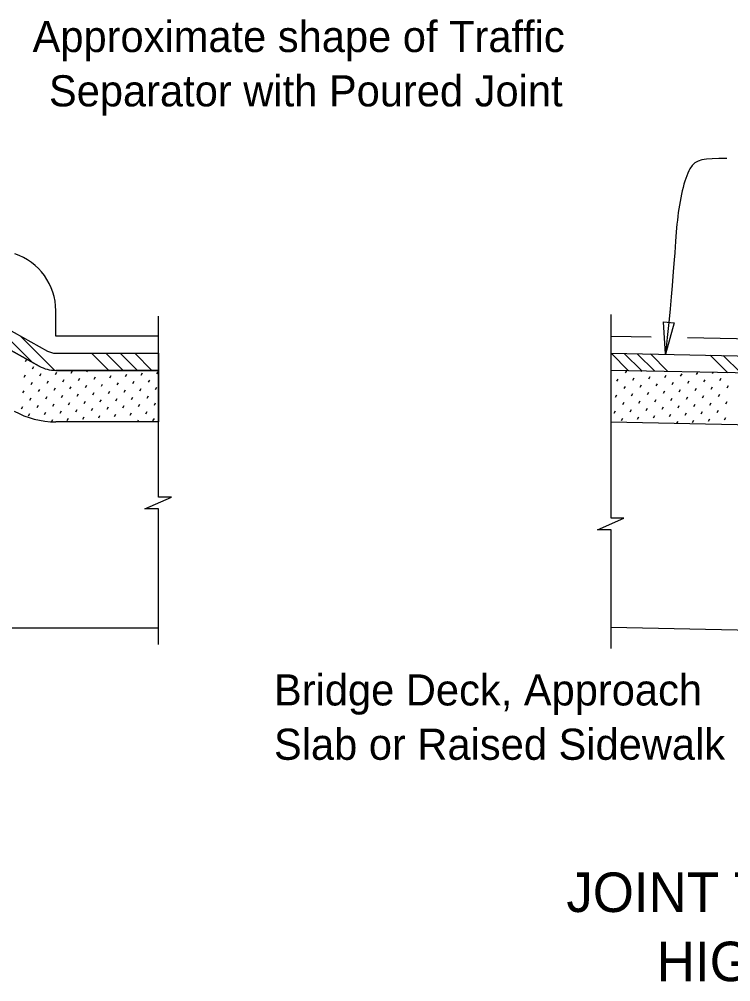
# Model space of a CAD drawing. Extents: x -7.9 to 27, y -3.1 to 14.6.
# Drawn here: x 9.806 to 11.534, y 7.031 to 9.368 of the extents above; entities that cross this region are included whole.
import ezdxf

# ---------------------------------------------------------------- set-up
doc = ezdxf.new("R2010")
doc.units = 0
for name, color, linetype in [('Patterning', 7, 'Continuous'), ('PlotBorder_dp', 7, 'Continuous'), ('TextMisc', 7, 'Continuous')]:
    doc.layers.add(name, color=color, linetype=linetype)

msp = doc.modelspace()

# ---------------------------------------------------------------- linework, layer by layer
at = {"layer": 'Patterning'}
for p, q in [((9.8946, 8.5989), (9.8946, 8.6605)), ((11.2433, 8.599), (11.3407, 8.597)), ((11.429, 8.5953), (13.3109, 8.5576)), ((5.2585, 7.8906), (10.1444, 7.8906)), ((14.5636, 7.8243), (11.2433, 7.8907))]:
    msp.add_line(p, q, dxfattribs=at)
msp.add_lwpolyline([(10.1445, 8.599), (9.8947, 8.599)], dxfattribs=at)
msp.add_arc((9.7488, 8.6606), 0.1458, 0, 71.5651, dxfattribs=at)
at = {"layer": 'PlotBorder_dp'}
for points in [[(11.2432, 7.8402), (11.2432, 8.1284), (11.2102, 8.1284), (11.2742, 8.1567), (11.2432, 8.1567), (11.2432, 8.6517)], [(10.1444, 7.85), (10.1444, 8.1797), (10.1113, 8.1797), (10.1753, 8.208), (10.1444, 8.208), (10.1444, 8.6476)]]:
    msp.add_lwpolyline(points, dxfattribs=at)
msp.add_lwpolyline([(11.3966, 8.631), (11.3755, 8.5546), (11.3703, 8.6337)], close=True, dxfattribs=at)
msp.add_open_spline([(11.5243, 9.0302), (11.4677, 9.0302), (11.4308, 9.0302), (11.399, 8.8797), (11.3988, 8.7821), (11.3755, 8.5546)], degree=3, dxfattribs=at)
at = {"layer": 'TextMisc'}
for p, q in [((9.1426, 8.9691), (9.8744, 8.5625)), ((9.8542, 8.5261), (9.1405, 8.9226)), ((9.1405, 8.9226), (9.8542, 8.5261)), ((9.7296, 8.643), (9.8369, 8.5357)), ((9.8083, 8.5993), (9.8913, 8.5163)), ((9.8947, 8.5573), (10.1445, 8.5573)), ((9.9814, 8.5573), (10.0231, 8.5156)), ((10.0164, 8.5573), (10.0581, 8.5156)), ((10.0514, 8.5573), (10.0931, 8.5156)), ((10.0864, 8.5573), (10.1281, 8.5156)), ((10.1445, 8.5573), (10.1445, 8.5156)), ((11.2433, 8.5573), (11.2858, 8.5147)), ((11.2433, 8.5573), (13.3732, 8.5146)), ((11.2751, 8.5566), (11.3177, 8.5141)), ((9.821, 8.537), (9.8242, 8.5426)), ((11.307, 8.556), (11.3495, 8.5134)), ((11.3388, 8.5554), (11.3813, 8.5128)), ((11.4839, 8.5525), (11.5264, 8.5099)), ((11.5157, 8.5518), (11.5583, 8.5093)), ((9.8384, 8.5196), (9.8417, 8.5252)), ((9.8941, 8.5053), (9.8973, 8.5109)), ((10.1445, 8.5156), (9.8947, 8.5156)), ((9.8947, 8.5156), (10.1445, 8.5156)), ((9.9322, 8.5086), (9.9354, 8.5142)), ((9.9704, 8.5118), (9.9725, 8.5156)), ((10.0085, 8.5151), (10.0088, 8.5156)), ((10.1404, 8.5073), (10.1437, 8.5129)), ((10.1445, 8.5156), (10.1445, 8.3906)), ((13.3724, 8.4729), (11.2433, 8.5156)), ((11.2785, 8.5099), (11.2814, 8.5148)), ((11.3172, 8.5132), (11.3177, 8.5141)), ((11.4509, 8.5052), (11.4542, 8.5108)), ((11.4896, 8.5084), (11.4909, 8.5106)), ((9.8177, 8.4989), (9.821, 8.5045)), ((9.8352, 8.4814), (9.8384, 8.487)), ((9.8559, 8.5021), (9.8591, 8.5077)), ((9.8734, 8.4846), (9.8766, 8.4902)), ((9.9115, 8.4879), (9.9148, 8.4935)), ((9.9497, 8.4911), (9.9529, 8.4967)), ((9.9878, 8.4944), (9.9911, 8.5)), ((10.026, 8.4976), (10.0292, 8.5032)), ((10.0641, 8.5008), (10.0674, 8.5064)), ((10.0816, 8.4834), (10.0848, 8.489)), ((10.1023, 8.5041), (10.1055, 8.5097)), ((10.1197, 8.4866), (10.123, 8.4922)), ((11.2576, 8.489), (11.2608, 8.4946)), ((11.2962, 8.4922), (11.2995, 8.4978)), ((11.3349, 8.4954), (11.3381, 8.501)), ((11.3736, 8.4987), (11.3768, 8.5043)), ((11.3913, 8.481), (11.3945, 8.4866)), ((11.4122, 8.5019), (11.4155, 8.5075)), ((11.43, 8.4842), (11.4332, 8.4898)), ((11.4686, 8.4875), (11.4719, 8.493)), ((11.5073, 8.4907), (11.5105, 8.4963)), ((9.8145, 8.4607), (9.8177, 8.4663)), ((9.8527, 8.4639), (9.8559, 8.4695)), ((9.8908, 8.4672), (9.8941, 8.4728)), ((9.929, 8.4704), (9.9322, 8.476)), ((9.9671, 8.4737), (9.9704, 8.4793)), ((10.0053, 8.4769), (10.0085, 8.4825)), ((10.0227, 8.4595), (10.026, 8.465)), ((10.0434, 8.4801), (10.0467, 8.4857)), ((10.0609, 8.4627), (10.0641, 8.4683)), ((10.099, 8.4659), (10.1023, 8.4715)), ((10.1372, 8.4692), (10.1404, 8.4748)), ((11.2753, 8.4712), (11.2785, 8.4768)), ((11.314, 8.4745), (11.3172, 8.4801)), ((11.3526, 8.4777), (11.3559, 8.4833)), ((11.3703, 8.46), (11.3736, 8.4656)), ((11.409, 8.4633), (11.4122, 8.4689)), ((11.4477, 8.4665), (11.4509, 8.4721)), ((11.4863, 8.4697), (11.4896, 8.4753)), ((11.525, 8.473), (11.5283, 8.4786)), ((9.832, 8.4432), (9.8352, 8.4488)), ((9.8701, 8.4465), (9.8734, 8.4521)), ((9.9083, 8.4497), (9.9115, 8.4553)), ((9.9464, 8.453), (9.9497, 8.4586)), ((9.9639, 8.4355), (9.9671, 8.4411)), ((9.9846, 8.4562), (9.9878, 8.4618)), ((10.002, 8.4388), (10.0053, 8.4444)), ((10.0402, 8.442), (10.0434, 8.4476)), ((10.0783, 8.4452), (10.0816, 8.4508)), ((10.1165, 8.4485), (10.1197, 8.4541)), ((11.2543, 8.4503), (11.2576, 8.4559)), ((11.293, 8.4535), (11.2962, 8.4591)), ((11.3107, 8.4358), (11.314, 8.4414)), ((11.3317, 8.4568), (11.3349, 8.4624)), ((11.3494, 8.4391), (11.3526, 8.4447)), ((11.3881, 8.4423), (11.3913, 8.4479)), ((11.4267, 8.4455), (11.43, 8.4511)), ((11.4654, 8.4488), (11.4686, 8.4544)), ((11.5041, 8.452), (11.5073, 8.4576)), ((11.5218, 8.4343), (11.525, 8.4399)), ((9.8113, 8.4225), (9.8145, 8.4281)), ((9.8494, 8.4258), (9.8527, 8.4314)), ((9.8876, 8.429), (9.8908, 8.4346)), ((9.905, 8.4116), (9.9083, 8.4172)), ((9.9257, 8.4323), (9.929, 8.4379)), ((9.9432, 8.4148), (9.9464, 8.4204)), ((9.9813, 8.4181), (9.9846, 8.4237)), ((10.0195, 8.4213), (10.0227, 8.4269)), ((10.0576, 8.4245), (10.0609, 8.4301)), ((10.0958, 8.4278), (10.099, 8.4334)), ((10.134, 8.431), (10.1372, 8.4366)), ((11.2511, 8.4116), (11.2543, 8.4172)), ((11.272, 8.4326), (11.2753, 8.4382)), ((11.2898, 8.4149), (11.293, 8.4205)), ((11.3284, 8.4181), (11.3317, 8.4237)), ((11.3671, 8.4213), (11.3703, 8.4269)), ((11.4058, 8.4246), (11.409, 8.4302)), ((11.4444, 8.4278), (11.4477, 8.4334)), ((11.4831, 8.4311), (11.4863, 8.4367)), ((11.5008, 8.4134), (11.5041, 8.4189)), ((9.8287, 8.4051), (9.832, 8.4107)), ((9.8669, 8.4083), (9.8701, 8.4139)), ((9.8843, 8.3909), (9.8876, 8.3965)), ((9.9225, 8.3941), (9.9257, 8.3997)), ((9.9606, 8.3974), (9.9639, 8.403)), ((9.9988, 8.4006), (10.002, 8.4062)), ((10.0369, 8.4038), (10.0402, 8.4094)), ((10.0751, 8.4071), (10.0783, 8.4127)), ((10.0931, 8.3906), (10.0958, 8.3952)), ((10.1133, 8.4103), (10.1165, 8.4159)), ((10.1307, 8.3929), (10.134, 8.3985)), ((11.2688, 8.3939), (11.272, 8.3995)), ((11.3075, 8.3971), (11.3107, 8.4027)), ((11.3461, 8.4004), (11.3494, 8.406)), ((11.3848, 8.4036), (11.3881, 8.4092)), ((11.4235, 8.4069), (11.4267, 8.4125)), ((11.4412, 8.3892), (11.4444, 8.3948)), ((11.4621, 8.4101), (11.4654, 8.4157)), ((11.4799, 8.3924), (11.4831, 8.398)), ((11.5185, 8.3956), (11.5218, 8.4012)), ((10.1445, 8.3906), (9.8947, 8.3906)), ((10.0568, 8.3906), (10.0576, 8.392)), ((11.2433, 8.3905), (13.3909, 8.3476)), ((11.367, 8.3881), (11.3671, 8.3883)), ((11.4033, 8.3873), (11.4058, 8.3915))]:
    msp.add_line(p, q, dxfattribs=at)
for centre, radius in [((9.8947, 8.599), 0.0417), ((9.8947, 8.5989), 0.0833), ((9.8947, 8.5989), 0.0833), ((9.8947, 8.5989), 0.2083)]:
    msp.add_arc(centre, radius, 240.9449, 269.9997, dxfattribs=at)

# ---------------------------------------------------------------- texts
at = {"layer": 'PlotBorder_dp'}
for s, height, p in [('Approximate shape of Traffic', 0.0756, (9.8383, 9.2888)), ('Separator with Poured Joint', 0.0756, (9.878, 9.1568)), ('Bridge Deck, Approach ', 0.0756, (10.4245, 7.7017)), ('Slab or Raised Sidewalk', 0.0756, (10.4245, 7.5697)), ('JOINT TREATMENT AT LOW SIDE OF DECK OR', 0.096, (11.1347, 7.2)), ('HIGH SIDE OF DECK WITH SLOPES < 1%', 0.096, (11.3543, 7.032))]:
    msp.add_text(s, height=height, dxfattribs=at).set_placement(p)

doc.saveas('drawing.dxf')
